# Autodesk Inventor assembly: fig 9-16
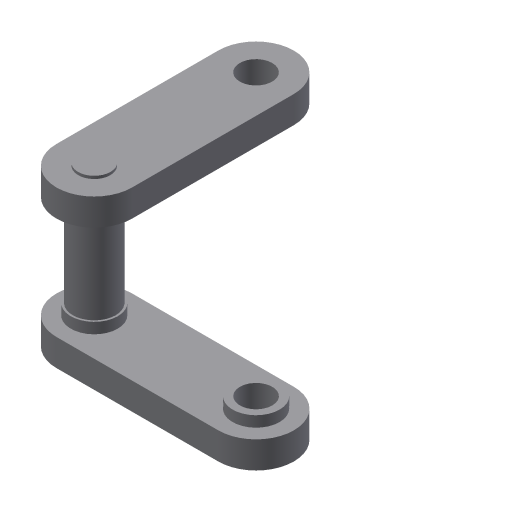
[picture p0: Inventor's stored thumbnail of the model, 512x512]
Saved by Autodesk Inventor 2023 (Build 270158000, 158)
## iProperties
Created: 2002-01
Part Number: fig 9-16
Document SubType Name: Assembly
Designer: ***
Control State: 0
Master: False
Checked Out: False
Shininess: 64.0
Length Units: 11269
Angle Units: 11279
Time Units: 11290
Mass Units: 11283
Length Display Precision: 3
Angle Display Precision: 2
Density: 0.0
Volumn: 0.0
Area: 0.0
PropertySet Name: Model Information
Author: ***
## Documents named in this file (3)
- D:\PROJECTS\Project 2022\Autodesk Inventor For Professional 2023\RESOURCES INVENTOR 2023\RESOURCES INVENTOR 2023\Inventor_2023_Part\Inventor_2023_Part\c09_Inv_2023_prt\fig 9-16.iam
- D:\PROJECTS\Project 2022\Autodesk Inventor For Professional 2023\RESOURCES INVENTOR 2023\RESOURCES INVENTOR 2023\Inventor_2023_Part\Inventor_2023_Part\c09_Inv_2023_prt\Part5.ipt
- D:\PROJECTS\Project 2022\Autodesk Inventor For Professional 2023\RESOURCES INVENTOR 2023\RESOURCES INVENTOR 2023\Inventor_2023_Part\Inventor_2023_Part\c09_Inv_2023_prt\Part6.ipt
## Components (3 placed, 2 different names)
1. Part5:1 — Insert:1, Angle:1
2. Part6:1 — Insert:1, Insert:2
3. Part5:2 — Insert:2, Angle:1
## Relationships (3: Insert 2, Angle 1)
- Insert:1: Part5:1 ↔ Part6:1
- Insert:2: Part6:1 ↔ Part5:2
- Angle:1: Part5:1 ↔ Part5:2
